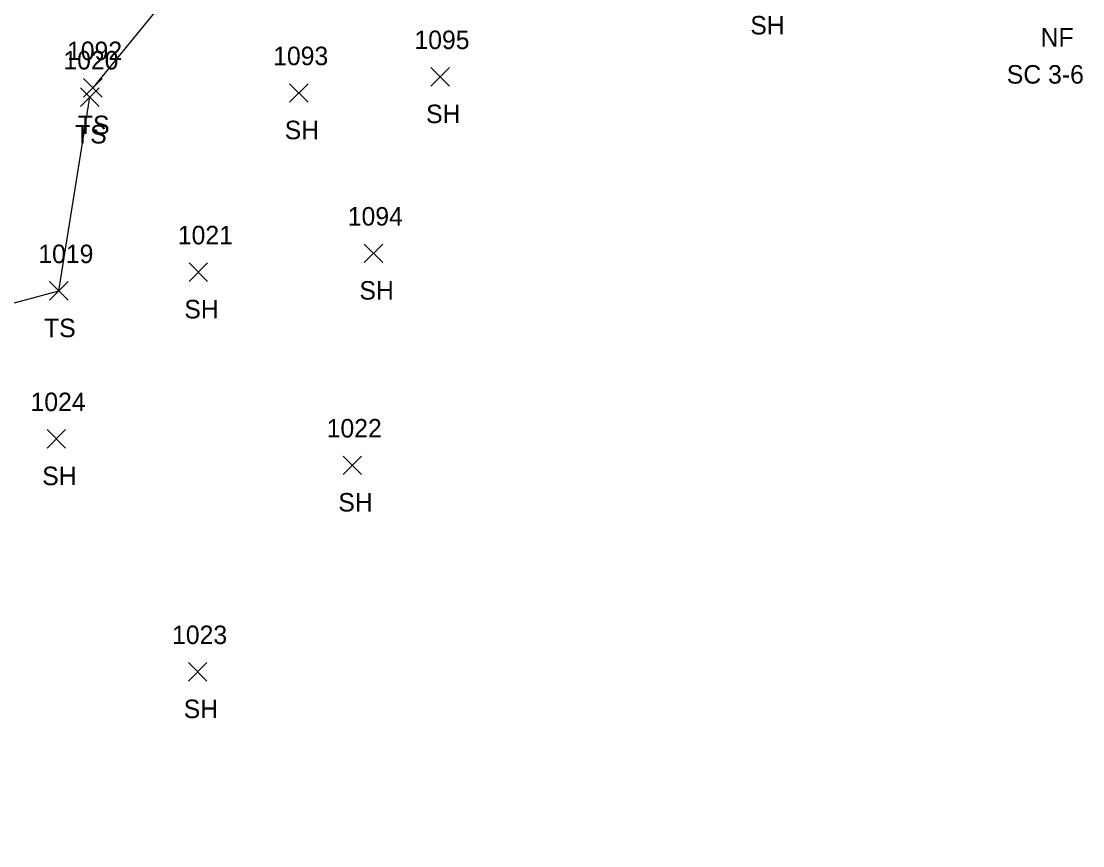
# Model space of a CAD drawing. Extents: x 1528286 to 1556263, y 492387 to 508952.
# Drawn here: x 1528710.1 to 1528824.8, y 492704.9 to 492794 of the extents above; entities that cross this region are included whole.
import ezdxf

# ---------------------------------------------------------------- set-up
doc = ezdxf.new("R2010")
doc.units = 0
for name, color, linetype in [('L_A', 7, 'Continuous'), ('L_C', 7, 'Continuous'), ('L_I', 7, 'Continuous'), ('L_TIC', 7, 'Continuous'), ('LELB', 7, 'Continuous')]:
    doc.layers.add(name, color=color, linetype=linetype)

msp = doc.modelspace()

# ---------------------------------------------------------------- linework, layer by layer
at = {"layer": 'L_TIC'}
for points in [[(1528754.36, 492787.03), (1528756.36, 492789.03)], [(1528756.36, 492787.03), (1528754.36, 492789.03)], [(1528754.36, 492787.03), (1528756.36, 492789.03)], [(1528756.36, 492787.03), (1528754.36, 492789.03)], [(1528716.83, 492785.84), (1528718.83, 492787.84)], [(1528718.83, 492785.84), (1528716.83, 492787.84)], [(1528716.83, 492785.84), (1528718.83, 492787.84)], [(1528718.83, 492785.84), (1528716.83, 492787.84)], [(1528716.51, 492784.83), (1528718.51, 492786.83)], [(1528718.51, 492784.83), (1528716.51, 492786.83)], [(1528716.51, 492784.83), (1528718.51, 492786.83)], [(1528718.51, 492784.83), (1528716.51, 492786.83)], [(1528739.09, 492785.29), (1528741.09, 492787.29)], [(1528741.09, 492785.29), (1528739.09, 492787.29)], [(1528739.09, 492785.29), (1528741.09, 492787.29)], [(1528741.09, 492785.29), (1528739.09, 492787.29)], [(1528747.16, 492767.96), (1528749.16, 492769.96)], [(1528749.16, 492767.96), (1528747.16, 492769.96)], [(1528747.16, 492767.96), (1528749.16, 492769.96)], [(1528749.16, 492767.96), (1528747.16, 492769.96)], [(1528728.23, 492765.93), (1528730.23, 492767.93)], [(1528730.23, 492765.93), (1528728.23, 492767.93)], [(1528728.23, 492765.93), (1528730.23, 492767.93)], [(1528730.23, 492765.93), (1528728.23, 492767.93)], [(1528713.16, 492763.9), (1528715.16, 492765.9)], [(1528715.16, 492763.9), (1528713.16, 492765.9)], [(1528713.16, 492763.9), (1528715.16, 492765.9)], [(1528715.16, 492763.9), (1528713.16, 492765.9)], [(1528712.89, 492747.91), (1528714.89, 492749.91)], [(1528714.89, 492747.91), (1528712.89, 492749.91)], [(1528712.89, 492747.91), (1528714.89, 492749.91)], [(1528714.89, 492747.91), (1528712.89, 492749.91)], [(1528744.87, 492745.06), (1528746.87, 492747.06)], [(1528746.87, 492745.06), (1528744.87, 492747.06)], [(1528744.87, 492745.06), (1528746.87, 492747.06)], [(1528746.87, 492745.06), (1528744.87, 492747.06)], [(1528728.17, 492722.74), (1528730.17, 492724.74)], [(1528730.17, 492722.74), (1528728.17, 492724.74)], [(1528728.17, 492722.74), (1528730.17, 492724.74)], [(1528730.17, 492722.74), (1528728.17, 492724.74)]]:
    msp.add_lwpolyline(points, dxfattribs=at)
at = {"layer": 'LELB'}
for points in [[(1528771.37, 492833.54), (1528753.46, 492821.03), (1528741.18, 492811.6), (1528730.18, 492801.97), (1528717.83, 492786.84)], [(1528771.37, 492833.54), (1528753.46, 492821.03), (1528741.18, 492811.6), (1528730.18, 492801.97), (1528717.83, 492786.84)], [(1528705.26, 492704.94), (1528686.12, 492722.49), (1528693.64, 492743.1), (1528696.25, 492760.07), (1528714.16, 492764.9), (1528717.51, 492785.83)], [(1528705.26, 492704.94), (1528686.12, 492722.49), (1528693.64, 492743.1), (1528696.25, 492760.07), (1528714.16, 492764.9), (1528717.51, 492785.83)]]:
    msp.add_lwpolyline(points, dxfattribs=at)

# ---------------------------------------------------------------- texts
at = {"layer": 'L_A'}
for s, p in [('SH', (1528788.86, 492792.61)), ('SH', (1528788.86, 492792.61)), ('NF', (1528820.22, 492791.3)), ('NF', (1528820.22, 492791.3)), ('SH', (1528753.84, 492783.03)), ('SH', (1528753.84, 492783.03)), ('TS', (1528716.23, 492781.84)), ('TS', (1528716.23, 492781.84)), ('SH', (1528738.57, 492781.29)), ('SH', (1528738.57, 492781.29)), ('TS', (1528715.92, 492780.83)), ('TS', (1528715.92, 492780.83)), ('SH', (1528746.64, 492763.96)), ('SH', (1528746.64, 492763.96)), ('SH', (1528727.72, 492761.93)), ('SH', (1528727.72, 492761.93)), ('TS', (1528712.57, 492759.9)), ('TS', (1528712.57, 492759.9)), ('SH', (1528712.37, 492743.91)), ('SH', (1528712.37, 492743.91)), ('SH', (1528744.36, 492741.06)), ('SH', (1528744.36, 492741.06)), ('SH', (1528727.66, 492718.74)), ('SH', (1528727.66, 492718.74))]:
    msp.add_text(s, height=2, dxfattribs=at).set_placement(p)
at = {"layer": 'L_C'}
msp.add_text('SC 3-6', height=2, dxfattribs=at).set_placement((1528816.57, 492787.3))
msp.add_text('SC 3-6', height=2, dxfattribs=at).set_placement((1528816.57, 492787.3))
at = {"layer": 'L_I'}
for s, p in [('1095', (1528752.58, 492791.03)), ('1095', (1528752.58, 492791.03)), ('1092', (1528715.05, 492789.84)), ('1092', (1528715.05, 492789.84)), ('1093', (1528737.32, 492789.29)), ('1093', (1528737.32, 492789.29)), ('1020', (1528714.66, 492788.83)), ('1020', (1528714.66, 492788.83)), ('1094', (1528745.38, 492771.96)), ('1094', (1528745.38, 492771.96)), ('1021', (1528727.02, 492769.93)), ('1021', (1528727.02, 492769.93)), ('1019', (1528711.95, 492767.9)), ('1019', (1528711.95, 492767.9)), ('1024', (1528711.11, 492751.91)), ('1024', (1528711.11, 492751.91)), ('1022', (1528743.1, 492749.06)), ('1022', (1528743.1, 492749.06)), ('1023', (1528726.4, 492726.74)), ('1023', (1528726.4, 492726.74))]:
    msp.add_text(s, height=2, dxfattribs=at).set_placement(p)

doc.saveas('drawing.dxf')
